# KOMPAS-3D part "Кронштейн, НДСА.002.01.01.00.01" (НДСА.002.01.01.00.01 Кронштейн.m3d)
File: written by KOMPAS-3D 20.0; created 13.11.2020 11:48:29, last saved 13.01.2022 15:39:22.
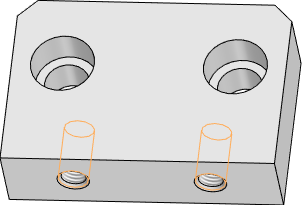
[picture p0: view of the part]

Document properties: Автор: 111; Полное имя файла: C:\Users\korychko\Desktop\PLM\НДСА.002.01.01.00.01 Кронштейн.m3d

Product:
- Part/product: Кронштейн  | designation НДСА.002.01.01.00.01
    Материал: Д16  ГОСТ 4784-97 (density 2800 kg/m3)
    Масса: 0.178026
    additional columns: <item xmlns="http://appius.ru/pdm" xmlns:xs="http://www.w3.org/2001/XMLSchema" x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; <item xmlns="http://appius.ru/pdm" xmlns:xs="http://www.w3.org/2001/XMLSchema" x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; <item xmlns="http://appius.ru/pdm" xmlns:xs="http://www.w3.org/2001/XMLSchema" x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
    source file: НДСА.002.01.01.00.01 Кронштейн.cdw

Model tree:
1. Эскиз:1
2. Элемент выдавливания:1
     Расстояние 1 = 135
3. Эскиз:2  (with: Элемент выдавливания:1)
4. Элемент выдавливания:2
     Расстояние 2 = 30
5. Эскиз:4  (with: Элемент выдавливания:1, Элемент выдавливания:2)
6. Элемент выдавливания:4
     Расстояние 2 = 20
7. Элемент выдавливания:5  (with: Элемент выдавливания:1)
     Расстояние 2 = 20
8. Элемент выдавливания:6  (with: Элемент выдавливания:1)
     Расстояние 2 = 12
9. Эскиз:5  (with: Элемент выдавливания:1, Элемент выдавливания:6)
10. Элемент выдавливания:7
     Расстояние 2 = 10
11. Элемент выдавливания:9  (with: Элемент выдавливания:7)
     Расстояние 2 = 0.5
12. Элемент выдавливания:10  (with: Элемент выдавливания:7)
     Расстояние 2 = 0.5
13. Элемент выдавливания:11  (with: Элемент выдавливания:1)
     Расстояние 2 = 0.5
14. Фаска:2  (with: Элемент выдавливания:11)
     Угол = 45; Длина 1 = 5; Длина 2 = 5
15. Эскиз:19  (with: Элемент выдавливания:1, Элемент выдавливания:11)
16. Элемент выдавливания:12
     Расстояние 2 = 10
17. Элемент выдавливания:13  (with: Элемент выдавливания:1)
     Расстояние 2 = 18.5
18. Элемент выдавливания:14  (with: Элемент выдавливания:6)
     Расстояние 2 = 11.5
19. Эскиз:20  (with: Элемент выдавливания:1)
20. Элемент выдавливания:15  (with: Элемент выдавливания:1)
     Расстояние 2 = 20
21. Эскиз:21  (with: Элемент выдавливания:15, Элемент выдавливания:1)
22. Отверстие:1  (with: Элемент выдавливания:15, Элемент выдавливания:1, Элемент выдавливания:10)  (labels: M8)
     Глубина выреза = 19; Диаметр отверстия = 6.64684; Угол конуса дна = 118; Расстояние 1 = 10; Расстояние 2 = -54.75; Диаметр зенковки = 8.64684; Глубина зенковки = 1; Угол зенковки = 90
23. M8  (labels: M8; cil0_24705-2004 coarse)
     Длина резьбы = 16; Шаг резьбы = 1.25; Номинальный диаметр резьбы = 8
24. Отверстие:2  (with: Элемент выдавливания:15, Элемент выдавливания:1, Элемент выдавливания:10, M8)  (labels: M8; cil0_24705-2004 coarse)
     Глубина выреза = 19; Диаметр отверстия = 6.64684; Угол конуса дна = 118; Расстояние 1 = 10; Расстояние 2 = -18.25; Диаметр зенковки = 8.64684; Глубина зенковки = 1; Угол зенковки = 90; Длина резьбы = 16; Шаг резьбы = 1.25; Номинальный диаметр резьбы = 8
25. Эскиз:22  (with: Элемент выдавливания:1, Элемент выдавливания:4)
26. Элемент выдавливания:16  (labels: Д16  ГОСТ 4784-97)
     Расстояние 2 = 10

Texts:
  НДСА.002.01.01.00.01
